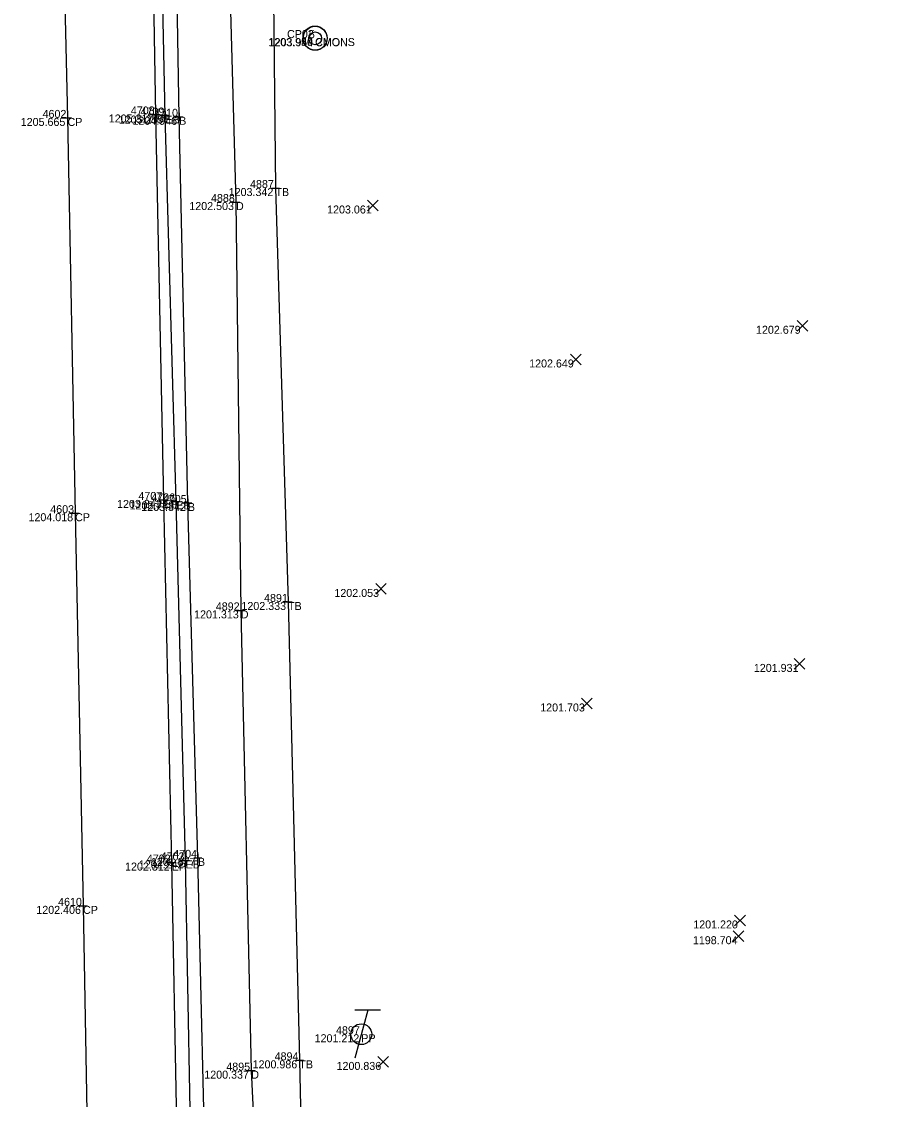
# Model space of a CAD drawing. Extents: x 2044996 to 2050343, y 455232 to 458054.
# Drawn here: x 2047634 to 2047743.9, y 456516 to 456650.7 of the extents above; entities that cross this region are included whole.
import ezdxf

# ---------------------------------------------------------------- set-up
doc = ezdxf.new("R2010")
doc.units = 0
for name, color, linetype in [('DR_X_Ditch', 7, 'Continuous'), ('DT_X_Contour_Minor', 7, 'Continuous'), ('DT_X_Contour_Text', 7, 'Continuous'), ('DT_X_Spot_Elev', 7, 'Continuous'), ('DT_X_Triangles', 7, 'Continuous'), ('DT_X_Void', 7, 'Continuous'), ('PV_X_COP', 7, 'Continuous'), ('PV_X_EOP', 7, 'Continuous'), ('PV_X_Shoulder_Aggregate', 7, 'Continuous'), ('SV_P_Mon_Cells_Set', 7, 'Continuous'), ('SV_X_Break_Lines', 7, 'Continuous'), ('SV_X_Top_of_Bank', 7, 'Continuous'), ('UT_X_Electric_Cells', 7, 'Continuous'), ('XS_X_Ground_Line', 7, 'Continuous')]:
    doc.layers.add(name, color=color, linetype=linetype)

msp = doc.modelspace()

# ---------------------------------------------------------------- linework, layer by layer
at = {"layer": 'DR_X_Ditch'}
msp.add_lwpolyline([(2047944.96, 456861.76), (2047899.25, 456878.16), (2047861.64, 456891.96), (2047815.35, 456909.09), (2047774.86, 456921.86), (2047729.93, 456938.25), (2047691.42, 456950.76), (2047669.22, 456956.37), (2047658.75, 456950.98), (2047651.4, 456909.49), (2047651.98, 456861.4), (2047653.43, 456816.89), (2047656.94, 456761.43), (2047657.83, 456718.94), (2047659.36, 456677.43), (2047660.77, 456628.12), (2047661.37, 456577.1), (2047662.68, 456519.59), (2047665.25, 456466.46), (2047666.16, 456418.54), (2047665.56, 456406.95)], dxfattribs=at)
at = {"layer": 'DT_X_Spot_Elev'}
for p, q in [((2047677.21, 456627.02), (2047678.55, 456628.36)), ((2047677.21, 456628.36), (2047678.55, 456627.02)), ((2047730.91, 456612), (2047732.25, 456613.33)), ((2047730.91, 456613.33), (2047732.25, 456612)), ((2047702.56, 456607.78), (2047703.9, 456609.12)), ((2047702.56, 456609.12), (2047703.9, 456607.78)), ((2047678.23, 456579.11), (2047679.56, 456580.45)), ((2047678.23, 456580.45), (2047679.56, 456579.11)), ((2047730.54, 456569.74), (2047731.87, 456571.08)), ((2047730.54, 456571.08), (2047731.87, 456569.74)), ((2047703.95, 456564.8), (2047705.28, 456566.14)), ((2047703.95, 456566.14), (2047705.28, 456564.8)), ((2047723.09, 456537.69), (2047724.43, 456539.03)), ((2047723.09, 456539.03), (2047724.43, 456537.69)), ((2047722.91, 456535.72), (2047724.24, 456537.06)), ((2047722.91, 456537.06), (2047724.24, 456535.72)), ((2047678.51, 456520.01), (2047679.84, 456521.35)), ((2047678.51, 456521.35), (2047679.84, 456520.01))]:
    msp.add_line(p, q, dxfattribs=at)
at = {"layer": 'DT_X_Void'}
for p, q in [((2047639.22, 456638.63), (2047640.22, 456638.63)), ((2047639.72, 456639.13), (2047639.72, 456638.13)), ((2047639.72, 456638.63), (2047639.72, 456638.63)), ((2047650.25, 456639.06), (2047651.25, 456639.06)), ((2047650.75, 456639.56), (2047650.75, 456638.56)), ((2047650.75, 456639.06), (2047650.75, 456639.06)), ((2047651.44, 456638.93), (2047652.44, 456638.93)), ((2047651.94, 456639.43), (2047651.94, 456638.43)), ((2047651.94, 456638.93), (2047651.94, 456638.93)), ((2047653.17, 456638.77), (2047654.17, 456638.77)), ((2047653.67, 456639.27), (2047653.67, 456638.27)), ((2047653.67, 456638.77), (2047653.67, 456638.77)), ((2047665.2, 456629.87), (2047666.2, 456629.87)), ((2047665.7, 456630.37), (2047665.7, 456629.37)), ((2047665.7, 456629.87), (2047665.7, 456629.87)), ((2047660.27, 456628.12), (2047661.27, 456628.12)), ((2047660.77, 456628.62), (2047660.77, 456627.62)), ((2047660.77, 456628.12), (2047660.77, 456628.12)), ((2047651.24, 456590.9), (2047652.24, 456590.9)), ((2047651.74, 456591.4), (2047651.74, 456590.4)), ((2047651.74, 456590.9), (2047651.74, 456590.9)), ((2047652.8, 456590.72), (2047653.8, 456590.72)), ((2047653.3, 456591.22), (2047653.3, 456590.22)), ((2047653.3, 456590.72), (2047653.3, 456590.72)), ((2047654.26, 456590.52), (2047655.26, 456590.52)), ((2047654.76, 456591.02), (2047654.76, 456590.02)), ((2047654.76, 456590.52), (2047654.76, 456590.52)), ((2047640.17, 456589.24), (2047641.17, 456589.24)), ((2047640.67, 456589.74), (2047640.67, 456588.74)), ((2047640.67, 456589.24), (2047640.67, 456589.24)), ((2047666.78, 456578.15), (2047667.78, 456578.15)), ((2047667.28, 456578.65), (2047667.28, 456577.65)), ((2047667.28, 456578.15), (2047667.28, 456578.15)), ((2047660.87, 456577.1), (2047661.87, 456577.1)), ((2047661.37, 456577.6), (2047661.37, 456576.6)), ((2047661.37, 456577.1), (2047661.37, 456577.1)), ((2047652.74, 456546.09), (2047652.74, 456545.09)), ((2047653.97, 456545.86), (2047654.97, 456545.86)), ((2047654.47, 456546.36), (2047654.47, 456545.36)), ((2047654.47, 456545.86), (2047654.47, 456545.86)), ((2047655.52, 456546.18), (2047656.52, 456546.18)), ((2047656.02, 456546.68), (2047656.02, 456545.68)), ((2047656.02, 456546.18), (2047656.02, 456546.18)), ((2047652.24, 456545.59), (2047653.24, 456545.59)), ((2047652.74, 456545.59), (2047652.74, 456545.59)), ((2047641.66, 456540.68), (2047641.66, 456539.68)), ((2047641.16, 456540.18), (2047642.16, 456540.18)), ((2047641.66, 456540.18), (2047641.66, 456540.18)), ((2047662.68, 456520.09), (2047662.68, 456519.09)), ((2047668.19, 456520.88), (2047669.19, 456520.88)), ((2047668.69, 456521.38), (2047668.69, 456520.38)), ((2047668.69, 456520.88), (2047668.69, 456520.88)), ((2047662.18, 456519.59), (2047663.18, 456519.59)), ((2047662.68, 456519.59), (2047662.68, 456519.59))]:
    msp.add_line(p, q, dxfattribs=at)
at = {"layer": 'PV_X_COP'}
msp.add_lwpolyline([(2047638.65, 456684.97), (2047639.72, 456638.63), (2047640.67, 456589.24), (2047641.66, 456540.18), (2047642.52, 456493.32), (2047643.71, 456444.37), (2047644.36, 456399.72), (2047645.21, 456358.38), (2047646.69, 456312.13), (2047647.16, 456279.14), (2047647.64, 456246.5), (2047648.01, 456224.8), (2047648.98, 456176.78), (2047649.64, 456128.98), (2047650.62, 456077.99), (2047651.48, 456030.79), (2047652.41, 455980.92), (2047652.55, 455976.29)], dxfattribs=at)
at = {"layer": 'PV_X_EOP'}
for p, q in [((2047650.75, 456639.06), (2047649.89, 456688.04)), ((2047651.74, 456590.9), (2047650.75, 456639.06)), ((2047652.74, 456545.59), (2047651.74, 456590.9)), ((2047653.66, 456499.18), (2047652.74, 456545.59))]:
    msp.add_line(p, q, dxfattribs=at)
at = {"layer": 'PV_X_Shoulder_Aggregate'}
msp.add_lwpolyline([(2047664.76, 455980.11), (2047663.65, 456028.13), (2047662.66, 456078.84), (2047661.94, 456126.71), (2047661.18, 456172.4), (2047660.15, 456223.29), (2047659.21, 456276.46), (2047658.4, 456325.53), (2047657.58, 456370.17), (2047657.31, 456406.35), (2047656.24, 456454.32), (2047655.34, 456499.11), (2047654.47, 456545.86), (2047653.3, 456590.72), (2047651.94, 456638.93), (2047650.86, 456688.18)], dxfattribs=at)
at = {"layer": 'SV_P_Mon_Cells_Set'}
msp.add_circle((2047670.65, 456648.61), 1.5, dxfattribs=at)
at = {"layer": 'SV_X_Break_Lines'}
msp.add_lwpolyline([(2047658.43, 456406.25), (2047657.57, 456454.16), (2047657.12, 456499.13), (2047656.02, 456546.18), (2047654.76, 456590.52), (2047653.67, 456638.77), (2047652.84, 456687.95), (2047651.32, 456732.84), (2047649.31, 456778.74), (2047648.48, 456826.81), (2047647.99, 456872.14), (2047647.65, 456917.64), (2047648.11, 456940.22), (2047652.79, 456955.84)], dxfattribs=at)
at = {"layer": 'SV_X_Top_of_Bank'}
msp.add_lwpolyline([(2047942.14, 456857.99), (2047898.01, 456872.36), (2047859.06, 456885.19), (2047815.47, 456901.27), (2047771.85, 456916.42), (2047729.97, 456932.49), (2047688.22, 456947.3), (2047669.99, 456955.17), (2047661.07, 456948.62), (2047656.72, 456911.9), (2047659.76, 456864.17), (2047662.28, 456815.7), (2047662.72, 456763.39), (2047662.48, 456719.38), (2047665.2, 456677.14), (2047665.7, 456629.87), (2047667.28, 456578.15), (2047668.69, 456520.88), (2047669.88, 456466.8), (2047671, 456408.28)], dxfattribs=at)
at = {"layer": 'UT_X_Electric_Cells'}
for p, q in [((2047678.83, 456527.14), (2047675.63, 456527.14)), ((2047677.23, 456527.14), (2047675.63, 456521.14))]:
    msp.add_line(p, q, dxfattribs=at)
msp.add_circle((2047676.43, 456524.14), 1.3, dxfattribs=at)
at = {"layer": 'XS_X_Ground_Line'}
for radius in [1.5, 0.8]:
    msp.add_circle((2047670.67, 456648.58), radius, dxfattribs=at)

# ---------------------------------------------------------------- texts
at = {"layer": 'DT_X_Contour_Minor'}
for s, p in [('1203.950', (2047664.81, 456647.61)), ('1203.944', (2047664.86, 456647.58)), ('1205.665', (2047633.87, 456637.63)), ('1205.317', (2047644.87, 456638.06)), ('1205.259', (2047646.12, 456637.93)), ('1204.946', (2047647.83, 456637.77)), ('1203.342', (2047659.86, 456628.87)), ('1202.503', (2047654.94, 456627.12)), ('1203.061', (2047672.16, 456626.69)), ('1202.679', (2047725.76, 456611.66)), ('1202.649', (2047697.41, 456607.45)), ('1203.843', (2047645.91, 456589.9)), ('1203.738', (2047647.47, 456589.72)), ('1203.342', (2047648.93, 456589.52)), ('1204.018', (2047634.84, 456588.24)), ('1202.053', (2047673.07, 456578.78)), ('1202.333', (2047661.45, 456577.15)), ('1201.313', (2047655.54, 456576.1)), ('1201.931', (2047725.49, 456569.41)), ('1201.703', (2047698.79, 456564.47)), ('1202.242', (2047648.63, 456544.86)), ('1201.877', (2047650.14, 456545.18)), ('1202.312', (2047646.91, 456544.59)), ('1202.406', (2047635.82, 456539.18)), ('1201.220', (2047717.92, 456537.36)), ('1198.704', (2047717.87, 456535.39)), ('1201.212', (2047670.6, 456523.14)), ('1200.986', (2047662.85, 456519.88)), ('1200.836', (2047673.34, 456519.68)), ('1200.337', (2047656.81, 456518.59))]:
    msp.add_text(s, height=1, dxfattribs=at).set_placement(p)
at = {"layer": 'DT_X_Contour_Text'}
for s, p in [('CMONS', (2047670.65, 456647.61)), ('CMON', (2047670.67, 456647.58)), ('CP', (2047639.72, 456637.63)), ('EP', (2047650.75, 456638.06)), ('EB', (2047651.94, 456637.93)), ('B', (2047653.67, 456637.77)), ('TB', (2047665.7, 456628.87)), ('D', (2047660.77, 456627.12)), ('EP', (2047651.74, 456589.9)), ('EB', (2047653.3, 456589.72)), ('B', (2047654.76, 456589.52)), ('CP', (2047640.67, 456588.24)), ('TB', (2047667.28, 456577.15)), ('D', (2047661.37, 456576.1)), ('EB', (2047654.47, 456544.86)), ('B', (2047656.02, 456545.18)), ('EP', (2047652.74, 456544.59)), ('CP', (2047641.66, 456539.18)), ('PP', (2047676.43, 456523.14)), ('TB', (2047668.69, 456519.88)), ('D', (2047662.68, 456518.59))]:
    msp.add_text(s, height=1, dxfattribs=at).set_placement(p)
at = {"layer": 'DT_X_Triangles'}
for s, p in [('CP02', (2047667.15, 456648.61)), ('5', (2047669.87, 456648.58)), ('4708', (2047647.63, 456639.06)), ('4602', (2047636.6, 456638.63)), ('4709', (2047648.84, 456638.93)), ('4710', (2047650.55, 456638.77)), ('4887', (2047662.53, 456629.87)), ('4888', (2047657.65, 456628.12)), ('4707', (2047648.58, 456590.9)), ('4706', (2047650.18, 456590.72)), ('4705', (2047651.63, 456590.52)), ('4603', (2047637.56, 456589.24)), ('4892', (2047658.25, 456577.1)), ('4891', (2047664.28, 456578.15)), ('4704', (2047652.93, 456546.18)), ('4702', (2047649.63, 456545.59)), ('4703', (2047651.36, 456545.86)), ('4610', (2047638.54, 456540.18)), ('4897', (2047673.27, 456524.14)), ('4894', (2047665.6, 456520.88)), ('4895', (2047659.56, 456519.59))]:
    msp.add_text(s, height=1, dxfattribs=at).set_placement(p)

doc.saveas('drawing.dxf')
